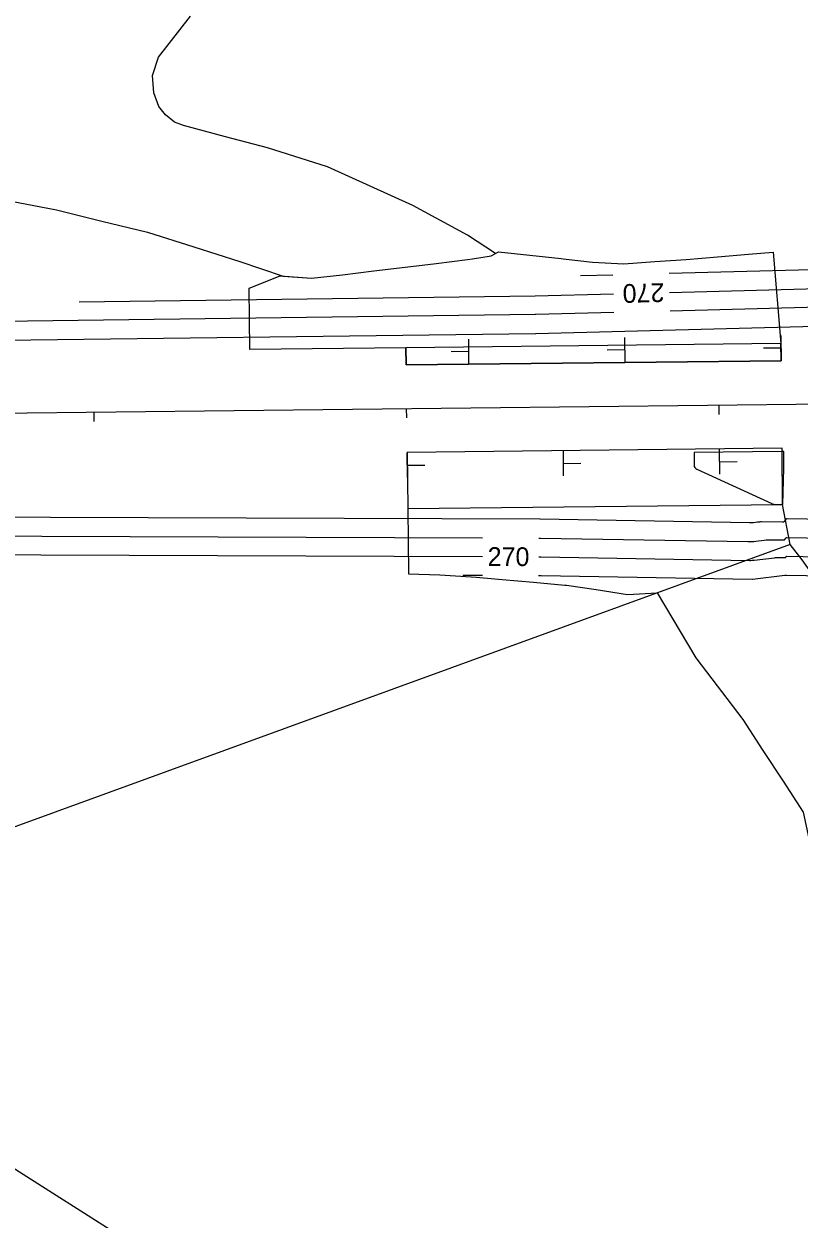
# Model space of a CAD drawing. Extents: x 1710723 to 1713003, y 548603 to 551142.
# Drawn here: x 1711418.2 to 1711666.3, y 548950.9 to 549333.3 of the extents above; entities that cross this region are included whole.
import ezdxf

# ---------------------------------------------------------------- set-up
doc = ezdxf.new("R2010")
doc.units = 0
for name, color, linetype in [('R_Contour Annot', 7, 'Continuous'), ('R_Contours', 7, 'Continuous'), ('R_Horz Alg', 7, 'Continuous'), ('R_Horz Alg Annot', 7, 'Continuous'), ('R_MOT', 7, 'Continuous'), ('R_No Plot', 7, 'Continuous'), ('R_Striping', 7, 'Continuous')]:
    doc.layers.add(name, color=color, linetype=linetype)

msp = doc.modelspace()

# ---------------------------------------------------------------- linework, layer by layer
at = {"layer": 'R_Contours'}
for points in [[(1711732.41, 549256.21), (1711624.73, 549253.39)], [(1711606.73, 549252.92), (1711596.33, 549252.64)], [(1711624.89, 549247.39), (1711732.23, 549250.21)], [(1711435.91, 549244.4), (1711581.84, 549246.26), (1711581.87, 549246.26), (1711581.9, 549246.26), (1711606.89, 549246.92)], [(1711732.38, 549244.21), (1711625.04, 549241.39)], [(1711394.82, 549231.87), (1711581.92, 549234.26), (1711581.96, 549234.26), (1711582.01, 549234.26), (1711582.05, 549234.26), (1711582.09, 549234.26), (1711732.57, 549238.21)], [(1711607.05, 549240.92), (1711582.02, 549240.26), (1711581.98, 549240.26), (1711581.94, 549240.26), (1711581.9, 549240.26), (1711581.85, 549240.26), (1711394.88, 549237.87)], [(1711693.99, 549174.4), (1711662.46, 549174.94), (1711662.3, 549174.93), (1711662.16, 549174.87), (1711662.04, 549174.79), (1711661.94, 549174.67), (1711661.57, 549174.1), (1711661.46, 549173.98), (1711661.34, 549173.89), (1711661.2, 549173.84), (1711661.04, 549173.83), (1711654.34, 549173.93), (1711654.02, 549173.93), (1711653.7, 549173.92), (1711653.38, 549173.9), (1711653.06, 549173.86), (1711651.78, 549173.71), (1711651.46, 549173.68), (1711651.14, 549173.66), (1711650.82, 549173.65), (1711650.5, 549173.65), (1711583.44, 549174.8), (1711583.41, 549174.8), (1711583.38, 549174.8), (1711395.23, 549175.51)], [(1711395.73, 549169.51), (1711565.01, 549168.87)], [(1711583.01, 549168.8), (1711583.4, 549168.8), (1711583.44, 549168.8), (1711583.48, 549168.8), (1711583.52, 549168.8), (1711583.56, 549168.8), (1711649.9, 549167.66), (1711650.56, 549167.66), (1711651.21, 549167.68), (1711651.85, 549167.72), (1711652.5, 549167.79), (1711655.11, 549168.1), (1711655.76, 549168.17), (1711656.42, 549168.21), (1711657.07, 549168.24), (1711657.73, 549168.24), (1711661.45, 549168.18), (1711661.56, 549168.19), (1711661.65, 549168.22), (1711661.74, 549168.28), (1711661.81, 549168.37), (1711662.06, 549168.75), (1711662.13, 549168.84), (1711662.22, 549168.9), (1711662.31, 549168.93), (1711662.42, 549168.94), (1711693.91, 549168.4)], [(1711393.99, 549163.52), (1711395.29, 549163.51), (1711395.3, 549163.51), (1711564.99, 549162.87)], [(1711582.99, 549162.8), (1711583.42, 549162.8), (1711583.49, 549162.8), (1711583.55, 549162.8), (1711583.61, 549162.8), (1711583.67, 549162.8), (1711650.6, 549161.65), (1711650.93, 549161.65), (1711651.27, 549161.66), (1711651.61, 549161.68), (1711651.95, 549161.72), (1711658.42, 549162.49), (1711658.78, 549162.52), (1711659.13, 549162.55), (1711659.49, 549162.56), (1711659.84, 549162.56), (1711661.86, 549162.53), (1711661.92, 549162.54), (1711661.97, 549162.55), (1711662.01, 549162.59), (1711662.05, 549162.63), (1711662.19, 549162.84), (1711662.23, 549162.89), (1711662.27, 549162.92), (1711662.32, 549162.94), (1711662.38, 549162.94), (1711693.83, 549162.4)], [(1711558.76, 549156.89), (1711564.97, 549156.87)], [(1711582.97, 549156.8), (1711583.48, 549156.8), (1711583.55, 549156.8), (1711583.61, 549156.8), (1711583.68, 549156.8), (1711583.75, 549156.8), (1711651.29, 549155.64), (1711651.31, 549155.64), (1711651.34, 549155.64), (1711651.37, 549155.64), (1711651.4, 549155.64), (1711661.74, 549156.88), (1711661.79, 549156.88), (1711661.85, 549156.88), (1711661.9, 549156.89), (1711661.96, 549156.89), (1711662.26, 549156.88), (1711662.27, 549156.88), (1711662.28, 549156.89), (1711662.29, 549156.89), (1711662.29, 549156.9), (1711662.31, 549156.93), (1711662.32, 549156.94), (1711662.33, 549156.94), (1711662.33, 549156.94), (1711662.34, 549156.95), (1711693.93, 549156.4)]]:
    msp.add_lwpolyline(points, dxfattribs=at)
msp.add_lwpolyline([(1711661.48, 549192.06), (1711661.43, 549196.05), (1711661.43, 549196.42), (1711661.42, 549196.44), (1711661.42, 549196.46), (1711661.4, 549196.47), (1711661.38, 549196.47), (1711661.02, 549196.5), (1711660.95, 549196.5), (1711660.88, 549196.5), (1711660.82, 549196.5), (1711660.75, 549196.5), (1711632.79, 549196.15), (1711632.75, 549196.14), (1711632.72, 549196.12), (1711632.71, 549196.1), (1711632.7, 549196.06), (1711632.75, 549192.15), (1711632.8, 549191.72), (1711632.96, 549191.36), (1711633.23, 549191.07), (1711633.59, 549190.84), (1711657.56, 549179.81), (1711657.89, 549179.68), (1711658.22, 549179.59), (1711658.57, 549179.53), (1711658.93, 549179.5), (1711661.06, 549179.47), (1711661.07, 549179.47), (1711661.08, 549179.47), (1711661.08, 549179.48), (1711661.09, 549179.49), (1711661.12, 549179.53), (1711661.12, 549179.54), (1711661.13, 549179.55), (1711661.13, 549179.56), (1711661.13, 549179.57), (1711661.47, 549191.04), (1711661.47, 549191.29), (1711661.48, 549191.55), (1711661.48, 549191.81)], close=True, dxfattribs=at)
at = {"layer": 'R_Horz Alg'}
msp.add_line((1711391.77, 549208.53), (1711733, 549212.35), dxfattribs=at)
at = {"layer": 'R_Horz Alg Annot'}
for points in [[(1711440.76, 549206.08), (1711440.73, 549209.07)], [(1711540.75, 549207.2), (1711540.72, 549210.2)], [(1711640.75, 549208.32), (1711640.71, 549211.32)]]:
    msp.add_lwpolyline(points, dxfattribs=at)
at = {"layer": 'R_MOT'}
for p, q in [((1711658.03, 549260.25), (1711660.49, 549231.04)), ((1711490.29, 549248.71), (1711500.24, 549252.66)), ((1711490.51, 549229.13), (1711490.29, 549248.71)), ((1711560.47, 549232.42), (1711560.56, 549224.42)), ((1711610.47, 549232.98), (1711610.56, 549224.98)), ((1711660.47, 549233.54), (1711660.56, 549225.54)), ((1711540.5, 549229.7), (1711490.51, 549229.13)), ((1711560.4, 549228.44), (1711554.94, 549228.38)), ((1711610.4, 549229), (1711604.94, 549228.94)), ((1711660.39, 549229.56), (1711654.93, 549229.5)), ((1711540.97, 549188.12), (1711540.88, 549196.12)), ((1711590.97, 549188.68), (1711590.88, 549196.68)), ((1711640.96, 549189.24), (1711640.87, 549197.24)), ((1711591.04, 549192.66), (1711596.5, 549192.72)), ((1711641.03, 549193.22), (1711646.49, 549193.28)), ((1711541.04, 549192.1), (1711546.5, 549192.16)), ((1711541.08, 549178.2), (1711541.31, 549157.31)), ((1711663.44, 549166.72), (1711661.07, 549179.55)), ((1711620.88, 549151.22), (1711620.88, 549151.22))]:
    msp.add_line(p, q, dxfattribs=at)
for points in [[(1711569.21, 549259.85), (1711560.18, 549265.67), (1711542.71, 549275.18), (1711529.07, 549281.36), (1711515.43, 549287.54), (1711496.21, 549293.64), (1711482.79, 549297.2), (1711469.36, 549300.75), (1711466.42, 549301.86), (1711463.54, 549304.2), (1711461.37, 549306.91), (1711459.86, 549311.27), (1711459.4, 549316.75), (1711461.31, 549322.63), (1711471.51, 549335.72)], [(1711326.59, 549264.25), (1711354.93, 549271.47), (1711360.65, 549272.96), (1711378.94, 549276.9), (1711399.05, 549278.14), (1711408.99, 549277.54), (1711428.62, 549273.81), (1711443.21, 549270.22), (1711457.79, 549266.63), (1711472.59, 549261.95), (1711487.39, 549257.27), (1711501.25, 549252.59)], [(1711500.24, 549252.66), (1711510.25, 549251.89), (1711520.24, 549253.04), (1711530.23, 549254.23), (1711540.21, 549255.46), (1711550.2, 549256.67), (1711560.19, 549257.88), (1711561.84, 549258.13), (1711561.85, 549258.13), (1711567.8, 549259.07), (1711570.16, 549260.38), (1711580.17, 549259.31), (1711590.19, 549258.2), (1711590.77, 549258.15), (1711600.2, 549257.08), (1711610.21, 549256.49), (1711620.2, 549257.29), (1711630.19, 549257.9), (1711640.18, 549258.81), (1711650.17, 549259.58), (1711658.03, 549260.25)], [(1711501.25, 549252.59), (1711510.25, 549251.89), (1711520.24, 549253.04), (1711530.23, 549254.23), (1711540.21, 549255.46), (1711550.2, 549256.67), (1711560.19, 549257.88), (1711561.84, 549258.13), (1711561.85, 549258.13), (1711567.8, 549259.07), (1711569.21, 549259.85)], [(1711660.49, 549231.04), (1711660.56, 549225.54), (1711540.56, 549224.2), (1711540.5, 549229.7)], [(1711661.07, 549179.55), (1711660.87, 549197.54), (1711540.88, 549196.2), (1711541.08, 549178.2)], [(1711808.51, 549014.46), (1711797.83, 549015.34), (1711780.72, 549024.22), (1711764.61, 549034.78), (1711754.93, 549047.27), (1711743.56, 549057.03), (1711737.29, 549064.07), (1711724.77, 549081.73), (1711723.01, 549081.72), (1711718.65, 549087.89), (1711708.97, 549101.92), (1711699.3, 549115.95), (1711689.62, 549129.98), (1711679.95, 549144.01), (1711667.27, 549161.8), (1711663.44, 549166.72)], [(1711541.31, 549157.31), (1711551.32, 549156.99), (1711561.33, 549156.39), (1711562.99, 549156.27), (1711563, 549156.27), (1711568.96, 549155.75), (1711571.34, 549155.55), (1711581.35, 549154.67), (1711591.36, 549153.76), (1711591.94, 549153.69), (1711601.37, 549152.37), (1711611.39, 549150.72), (1711620.88, 549151.22)], [(1711620.88, 549151.22), (1711633.24, 549130.45)], [(1711633.24, 549130.45), (1711648.31, 549110.73), (1711654.76, 549100.85), (1711661.21, 549090.97), (1711667.66, 549081.09), (1711669.8, 549071.12), (1711670.82, 549061.14), (1711671.85, 549051.16), (1711672.88, 549041.18), (1711673.91, 549031.19), (1711688.03, 549012.49)]]:
    msp.add_lwpolyline(points, dxfattribs=at)
at = {"layer": 'R_No Plot'}
for p, q in [((1711663.44, 549166.72), (1711305.56, 549036.46)), ((1711305.56, 549036.46), (1711761.78, 548747.53))]:
    msp.add_line(p, q, dxfattribs=at)
for points in [[(1711540.5, 549229.7), (1711540.56, 549224.2), (1711660.56, 549225.54), (1711660.49, 549231.04)], [(1711540.88, 549196.2), (1711541.08, 549178.2), (1711661.07, 549179.55), (1711660.87, 549197.54)]]:
    msp.add_lwpolyline(points, close=True, dxfattribs=at)
msp.add_lwpolyline([(1711667.27, 549161.8), (1711663.44, 549166.72)], dxfattribs=at)
at = {"layer": 'R_Striping'}
msp.add_line((1711391.77, 549208.53), (1711733, 549212.35), dxfattribs=at)

# ---------------------------------------------------------------- texts
at = {"layer": 'R_Contour Annot'}
for rotation, p in [(181.5023, (1711623.15, 549250.35)), (359.7834, (1711566.63, 549159.87))]:
    msp.add_text('270', height=6, rotation=rotation, dxfattribs=at).set_placement(p)

doc.saveas('drawing.dxf')
